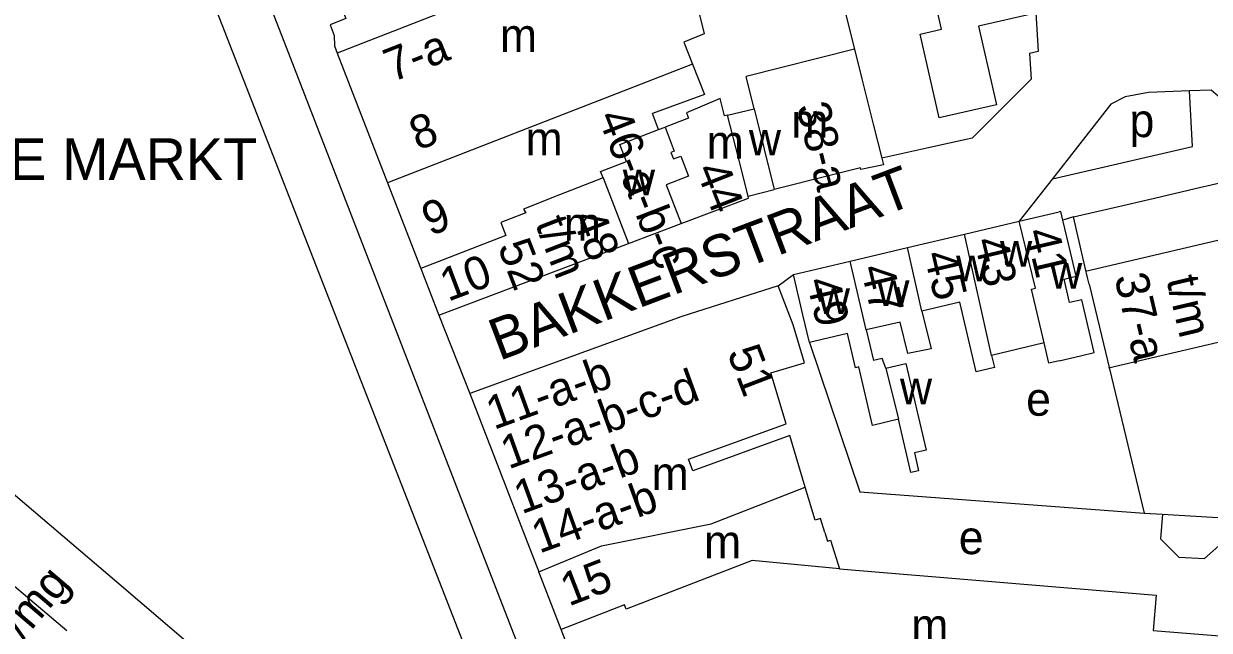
# Model space of a CAD drawing. Extents: x 159902 to 161769, y 383692 to 384875.
# Drawn here: x 160875.8 to 161018, y 384646.1 to 384718.9 of the extents above; entities that cross this region are included whole.
import ezdxf

# ---------------------------------------------------------------- set-up
doc = ezdxf.new("R2010")
doc.units = 0
for name, color, linetype in [('BLT_Basislijn', 7, 'Continuous'), ('BLT_Bebouwing', 7, 'Continuous'), ('BLT_Centroide', 7, 'Continuous'), ('BLT_Huisnummer', 7, 'Continuous'), ('BLT_Huisnummer_ tussenligend', 7, 'Continuous'), ('BLT_Huisnummer_reeks', 7, 'Continuous'), ('BLT_Huisnummer_zonder_bebouwing', 7, 'Continuous'), ('BLT_Onderdoorgang_en_onderverdeling', 7, 'Continuous'), ('BLT_Onderverdeling_panden', 7, 'Continuous'), ('BLT_Plantopo', 7, 'Continuous'), ('BLT_Straatnaam', 7, 'Continuous')]:
    doc.layers.add(name, color=color, linetype=linetype)

msp = doc.modelspace()

# ---------------------------------------------------------------- linework, layer by layer
at = {"layer": 'BLT_Basislijn'}
for p, q in [((160933.92, 384630.81), (160885.35, 384755.32)), ((160972.9, 384725.99), (160975.44, 384715.85)), ((160807.38, 384719.78), (160886.94, 384651.93)), ((160996.43, 384715.34), (160996.63, 384712.26)), ((160907.74, 384714.86), (160928.92, 384660.13)), ((160996.63, 384712.26), (160989.53, 384705.17)), ((161015.98, 384704.18), (161015.61, 384710.84)), ((160989.53, 384705.17), (160984.12, 384703.96)), ((160984.12, 384703.96), (160978.71, 384702.76)), ((160999.17, 384700.29), (161015.98, 384704.18)), ((160999.17, 384700.29), (160995.2, 384695.21)), ((161016.28, 384699.12), (161021.2, 384700.26)), ((161006.56, 384696.87), (161011.42, 384697.99)), ((161011.42, 384697.99), (161016.28, 384699.12)), ((161001.69, 384695.74), (161006.56, 384696.87)), ((161001.69, 384695.74), (161000.43, 384695.33)), ((160966.29, 384687.45), (160968.1, 384688.83)), ((161003.58, 384687.67), (161010.18, 384660.18)), ((160925.59, 384683.95), (160929.28, 384674.54)), ((160970.02, 384680.67), (160976.06, 384662.74)), ((160976.06, 384662.74), (161010.18, 384660.18)), ((160928.92, 384660.13), (160951.34, 384602.56))]:
    msp.add_line(p, q, dxfattribs=at)
for points in [[(160887.93, 384771.06), (160890.3, 384763.58), (160893.59, 384752.71), (160895.74, 384745.45), (160898.91, 384737.64), (160907.74, 384714.86)], [(160997.18, 384720.24), (160997.48, 384715.57), (160996.43, 384715.34)], [(161015.61, 384710.84), (161010.69, 384710.64), (161007.91, 384710.13), (161006.17, 384709.27), (160999.17, 384700.29)], [(161020.73, 384708.79), (161018.23, 384710.95), (161015.61, 384710.84)], [(161003.58, 384687.67), (161003.4, 384688.46), (161002.83, 384690.87), (161001.69, 384695.74)], [(161010.18, 384660.18), (161012.36, 384660.05)], [(160886.94, 384651.93), (160899.37, 384641.29), (160920.37, 384620.98)]]:
    msp.add_lwpolyline(points, dxfattribs=at)
at = {"layer": 'BLT_Bebouwing'}
for p, q in [((160913.38, 384715.36), (160919.42, 384699.82)), ((160975.44, 384715.85), (160962.42, 384712.59)), ((160975.44, 384715.85), (160976.32, 384712.29)), ((160960.21, 384707.95), (160963.39, 384708.71)), ((160951.93, 384706.23), (160952.72, 384706.5)), ((160955.53, 384707.56), (160952.72, 384706.5)), ((160919.42, 384699.82), (160923.41, 384689.54)), ((160972.32, 384700.65), (160965.81, 384699.01)), ((160962.66, 384698.22), (160965.81, 384699.01)), ((160988.63, 384693.66), (160995.2, 384695.21)), ((160995.2, 384695.21), (161000, 384696.34)), ((160948.33, 384692.54), (160954.63, 384694.92)), ((160925.59, 384683.95), (160948.33, 384692.54)), ((160981.77, 384692.05), (160988.63, 384693.66)), ((160974.91, 384690.43), (160981.77, 384692.05)), ((160923.41, 384689.54), (160925.59, 384683.95)), ((160968.1, 384688.83), (160974.91, 384690.43)), ((160976.85, 384682.16), (160977.72, 384678.49)), ((160940.23, 384646.21), (160937.56, 384653.13))]:
    msp.add_line(p, q, dxfattribs=at)
for points in [[(160909.28, 384732.74), (160914.41, 384719.53), (160912.53, 384718.77), (160913.02, 384717.51), (160913.04, 384716.26), (160913.38, 384715.36)], [(160953.85, 384731.19), (160954.09, 384731.25), (160957.39, 384717.71), (160954.96, 384716.71), (160956.01, 384714.04)], [(160956.01, 384714.04), (160957.43, 384710.41), (160951.21, 384708.13)], [(160963.39, 384708.71), (160962.42, 384712.59)], [(160976.32, 384712.29), (160977.69, 384706.84), (160978.71, 384702.76)], [(160959.31, 384709.93), (160955.28, 384708.21), (160955.53, 384707.56)], [(160960.21, 384707.95), (160959.84, 384707.85), (160959.31, 384709.93)], [(160951.93, 384706.23), (160951.21, 384708.13)], [(160978.71, 384702.76), (160978.9, 384701.99), (160976.21, 384701.41), (160976.17, 384701.62), (160972.32, 384700.65)], [(160954.63, 384694.92), (160962.72, 384697.97), (160962.66, 384698.22)], [(161000.43, 384695.33), (161000.18, 384696.38), (161000, 384696.34)], [(161000, 384678.47), (161002.54, 384679.07), (161004.19, 384679.45), (161002.7, 384685.78), (161001.24, 384685.44), (161000.58, 384688.27), (161002.01, 384688.61), (161001.82, 384689.45), (161001.33, 384691.51), (161000.43, 384695.33)], [(160970.02, 384680.67), (160969.24, 384683.97), (160968.1, 384688.83)], [(160966.29, 384687.45), (160954.73, 384683.79), (160929.28, 384674.54)], [(160955.52, 384666.64), (160967.25, 384670.9), (160965.41, 384677), (160969.44, 384678.2), (160968.09, 384682.77), (160966.29, 384687.45)], [(160991.87, 384679.11), (160992.22, 384677.66), (160990.04, 384677.15), (160988.08, 384685.49), (160983.52, 384684.41)], [(160983.52, 384684.41), (160984.62, 384679.9), (160981.81, 384679.34), (160980.92, 384683.11), (160976.85, 384682.16)], [(160980.72, 384671.45), (160977.61, 384670.71), (160975.96, 384677.72), (160975.57, 384677.63), (160974.6, 384681.75), (160970.02, 384680.67)], [(160998.17, 384680.6), (160991.87, 384679.11)], [(161000, 384678.47), (160998.74, 384678.17), (160998.17, 384680.6)], [(160979.19, 384677.57), (160978.74, 384678.73), (160977.72, 384678.49)], [(160979.19, 384677.57), (160981.59, 384678.13), (160984.03, 384667.73), (160982.61, 384667.4), (160983.11, 384665.26), (160982.2, 384665.05), (160980.72, 384671.45)], [(160929.28, 384674.54), (160933.51, 384663.59)], [(160969.52, 384663.31), (160967.66, 384669.49), (160956.02, 384665.26), (160955.52, 384666.64)], [(160933.51, 384663.59), (160935.41, 384658.68)], [(160971.86, 384657.86), (160971.36, 384659.52), (160970.73, 384659.33), (160969.52, 384663.31)], [(161012.36, 384660.05), (161012.12, 384657.09), (161014.34, 384654.91), (161017.4, 384654.72), (161019.49, 384656.59), (161021.52, 384655.26)], [(161012.36, 384660.05), (161025.05, 384659.3), (161025.5, 384658.8)], [(160935.41, 384658.68), (160937.56, 384653.13)], [(160971.86, 384657.86), (160972.18, 384656.8), (160972.56, 384656.92), (160973.65, 384653.51)], [(160973.65, 384653.51), (161011.61, 384650.35), (161011.27, 384646.09), (161023.71, 384645.1), (161023.19, 384638.65)], [(160880.96, 384646.06), (160874.66, 384651.39)], [(160944.57, 384634.97), (160940.23, 384646.21)]]:
    msp.add_lwpolyline(points, dxfattribs=at)
at = {"layer": 'BLT_Onderdoorgang_en_onderverdeling'}
msp.add_line((160963.39, 384708.71), (160965.81, 384699.01), dxfattribs=at)
msp.add_lwpolyline([(160962.66, 384698.22), (160961.5, 384702.82), (160960.21, 384707.95)], dxfattribs=at)
at = {"layer": 'BLT_Onderverdeling_panden'}
for p, q in [((160939.16, 384725.44), (160913.38, 384715.36)), ((160956.01, 384714.04), (160949.84, 384711.64)), ((160949.84, 384711.64), (160919.42, 384699.82)), ((160945.27, 384700.4), (160940.06, 384698.36)), ((160945.27, 384700.4), (160948.33, 384692.54)), ((160991.87, 384679.11), (160988.63, 384693.66)), ((160983.52, 384684.41), (160981.77, 384692.05)), ((160976.85, 384682.16), (160974.91, 384690.43)), ((160979.19, 384677.57), (160980.72, 384671.45))]:
    msp.add_line(p, q, dxfattribs=at)
for points in [[(160952.72, 384706.5), (160953.81, 384703.62), (160953.41, 384703.47)], [(160945.27, 384700.4), (160944.97, 384701.16), (160948.09, 384702.37), (160947.29, 384704.41), (160951.93, 384706.23)], [(160953.41, 384703.47), (160953.71, 384702.69), (160954.6, 384703.03), (160955.52, 384700.6), (160952.86, 384699.59), (160954.63, 384694.92)], [(160940.06, 384698.36), (160935.74, 384696.67), (160935.99, 384696.23), (160932.99, 384695.06), (160933.6, 384693.5), (160923.41, 384689.54)], [(160998.17, 384680.6), (160996.65, 384687.07), (160997.13, 384687.18), (160995.2, 384695.21)], [(160937.56, 384653.13), (160945.08, 384656.25), (160958.25, 384658.88), (160969.52, 384663.31)], [(160973.65, 384653.51), (160963.15, 384654.48), (160948.05, 384648.65), (160947.85, 384649.16), (160940.23, 384646.21)]]:
    msp.add_lwpolyline(points, dxfattribs=at)
at = {"layer": 'BLT_Plantopo'}
msp.add_lwpolyline([(160961.77, 384829.44), (160971.71, 384831.7), (160997, 384720.15), (160990.3, 384718.63), (160992.45, 384709.18), (160985.57, 384707.62), (160983.29, 384717.67), (160985.85, 384718.25), (160967.45, 384799.4), (160966.1, 384799.09), (160964.97, 384804.07), (160967.4, 384804.62)], close=True, dxfattribs=at)
msp.add_lwpolyline([(161003.14, 384689.21), (161024.83, 384694.29), (161025.44, 384691.67), (161028.31, 384692.34), (161030.99, 384680.94), (161026.6, 384679.91), (161026.04, 384682.29), (161005.88, 384677.56)], dxfattribs=at)

# ---------------------------------------------------------------- texts
at = {"layer": 'BLT_Centroide'}
for s, p in [('m', (160932.89, 384715.53)), ('m', (160967.84, 384705.25)), ('p', (161008.42, 384705.3)), ('m', (160935.97, 384703.12)), ('m', (160957.7, 384702.72)), ('w', (160962.76, 384703.1)), ('w', (160947.64, 384698.31)), ('m', (160940.56, 384692.88)), ('w', (160992.88, 384689.75)), ('w', (160987.61, 384688)), ('w', (160998.88, 384687.12)), ('w', (160978.15, 384685.03)), ('w', (160971.02, 384684.07)), ('w', (160980.88, 384673.25)), ('e', (160996.02, 384671.87)), ('m', (160951.09, 384662.94)), ('e', (160987.94, 384655.26)), ('m', (160957.38, 384654.75)), ('m', (160982.23, 384644.72))]:
    msp.add_text(s, height=4, dxfattribs=at).set_placement(p)
at = {"layer": 'BLT_Huisnummer'}
for s, rotation, p in [('44', 291.3642, (160956.35, 384701.41)), ('9', 21.3731, (160924.54, 384693.39)), ('41', 283.2472, (160995.94, 384693.95)), ('45', 283.2386, (160983.75, 384691.24)), ('49', 283.2522, (160969.64, 384688.05)), ('15', 21.114, (160941.15, 384648.96))]:
    msp.add_text(s, height=4, rotation=rotation, dxfattribs=at).set_placement(p)
at = {"layer": 'BLT_Huisnummer_ tussenligend'}
for s, rotation, p in [('43', 283.2472, (160989.76, 384692.87)), ('47', 283.2386, (160976.15, 384689.58))]:
    msp.add_text(s, height=4, rotation=rotation, dxfattribs=at).set_placement(p)
at = {"layer": 'BLT_Huisnummer_reeks'}
for s, rotation, p in [('7-a', 21.3605, (160919.97, 384711.86)), ('38-a', 284.0279, (160968.43, 384708.98)), ('8', 21.3609, (160923.04, 384703.65)), ('46-a-b-c', 291.2328, (160944.59, 384707.75)), ('t/m', 291.2328, (160937.08, 384694.94)), ('48', 291.2328, (160941.51, 384695.66)), ('52', 291.2328, (160932.58, 384692.17)), ('10', 20.6822, (160926.67, 384685.53)), ('51', 290.9805, (160960.12, 384679.45)), ('11-a-b', 19.969, (160932.17, 384670.15)), ('12-a-b-c-d', 19.969, (160933.92, 384665.41)), ('13-a-b', 19.969, (160935.5, 384660.03)), ('14-a-b', 19.969, (160937.62, 384655.31)), ('39-at/mg', 49.5779, (160867.8, 384635.62))]:
    msp.add_text(s, height=4, rotation=rotation, dxfattribs=at).set_placement(p)
at = {"layer": 'BLT_Huisnummer_zonder_bebouwing'}
for s, p in [('37-a', (161006.58, 384688.53)), ('t/m', (161012.82, 384688.22))]:
    msp.add_text(s, height=4, rotation=283.1967, dxfattribs=at).set_placement(p)
at = {"layer": 'BLT_Straatnaam'}
msp.add_text('WOENSELSE MARKT', height=5, dxfattribs=at).set_placement((160836.16, 384700.16))
msp.add_text('BAKKERSTRAAT', height=5, rotation=20.6822, dxfattribs=at).set_placement((160932.81, 384678.42))

doc.saveas('drawing.dxf')
